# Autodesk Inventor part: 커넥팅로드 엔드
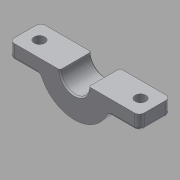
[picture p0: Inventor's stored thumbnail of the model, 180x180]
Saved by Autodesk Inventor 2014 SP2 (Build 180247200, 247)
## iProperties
Created: 2016-11
Part Number: 커넥팅로드 엔드
Material: 알루미늄 6061
Document SubType Name: Modeling
Designer: mduedu
Density: 2.71 g/cm^3
Mass: 15.0819 g
Surface Area: 26.6719 cm^2
Volume: 5.56529 cm^3
Appearance: 알루미늄 - 평지
Author: mduedu
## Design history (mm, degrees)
sketch "스케치1" dims "d0" = 30, "d3" = 15
  geometry: L1 (0, 0)-(0, 96); L2 (-5, 90.41)-(-10, 11.18); L3 (5, 90.41)-(10, 11.18); C1 r 6 at (0, 0); C2 r 4 at (0, 96); 3 further points
  constraints: 6 end point, 4 coincident, 2 centre point, 2 symmetric about line, 1 vertical, 6 other
  dimensions: "d1" = 12 diameter of C1; "d2" = 8 diameter of C2; "d4" = 96 distance of L1.start L1.end; "d6" = 10 distance from line of L1 L2.end; "d7" = 5 distance from line of L1 L2.start
extrude "돌출1" new body sketch "스케치1" stored distance "d8" = 13; taper "d9" = 0 deg
extrude "돌출2" join sketch "스케치1" stored distance "d10" = 32; taper "d11" = 0 deg
sketch "스케치2"
  geometry: L1 (5, 90.41)-(10, 11.18) reference; L2 (-5, 90.41)-(-10, 11.18) reference; A1 r 7.5 centre (0, 96) between (5, 90.41) and (-5, 90.41) reference; A2 r 15 centre (0, 0) between (10, 11.18) and (-10, 11.18) reference
extrude "돌출3" join sketch "스케치2" stored distance "d12" = 8; taper "d13" = 0 deg
sketch "스케치3"
  geometry: L1 (-2.732, 78.715)-(-6.171, 24.226); L2 (2.732, 78.715)-(6.171, 24.226); L3 (0, 78.5)-(0, 25); A1 r 17.5 centre (0, 96) between (-2.732, 78.715) and (2.732, 78.715); A2 r 25 centre (0, 0) between (6.171, 24.226) and (-6.171, 24.226); 9 further points; 2 other entities
  constraints: 6 end point, 6 point on circle, 2 centre point, 1 symmetric about line, 1 vertical alignment, 6 other
  dimensions: "d18" = 10 dimension on A1; "d19" = 10 dimension on A2; "d20" = 3 dimension on L1
extrude "돌출4" cut sketch "스케치3" distance "d21" = 2; taper "d22" = 0 deg
fillet "모깎기1" dims "d23" = 2
fillet "모깎기2" dims "d24" = 2
fillet "모깎기3" dims "d25" = 1
chamfer "모따기1" distance "d26" = 0.5; stored, may be unused: second distance "d27" = 2, angle "d28" = 45 deg
sketch "스케치4"
  geometry: L1 (-27, -6)-(-13.748, -6); L2 (27, -6)-(27, 6); L3 (27, 6)-(13.748, 6); L4 (-27, 6)-(-27, -6); L5 (-27, -6)-(27, 6); L6 (27, -6)-(-27, 6); L7 (-13.748, 6)-(-27, 6); L8 (13.748, 6)-(-13.748, 6); L9 (13.748, -6)-(27, -6); L10 (-13.748, -6)-(13.748, -6); A1 r 15 centre (0, 0) between (-13.748, 6) and (13.748, 6) reference; 1 further point
  constraints: 20 end point, 10 parallel, 4 point on circle, 3 horizontal, 3 perpendicular, 2 midpoint
  dimensions: "d29" = 54 distance of L1.start L2.start; "d31" = 12 distance of L2.start L2.end
extrude "돌출5" join sketch "스케치4" stored distance "d32" = 0; taper "d33" = 0 deg
fillet "모깎기4" dims "d34" = 2
fillet "모깎기5" dims "d35" = 1
fillet "모깎기6" dims "d36" = 1
sketch "스케치5"
  geometry: L1 (1, 0)-(1, 9) reference; L2 (-18.5, 20.5)-(-33.5, 20.5) reference; L3 (-33.5, -11.5)-(-18.5, -11.5) reference; L4 (-26, 20.5)-(-26, -11.5); 3 further points
  constraints: 2 end point, 2 midpoint, 1 horizontal alignment, 1 symmetric about line
  dimensions: "d37" = 6 distance from line of point (-5, 4.5) L1
feature "분할1"
sketch "스케치7"
  geometry: 2 further points
  constraints: 2 other
hole "구멍2" sketch "스케치7" at (-47, 4.5), (-5, 4.5) diameter "d45" = 4.5; stored, may be unused: countersink angle "d49" = 90 deg, drill point angle "d51" = 0 deg; dims "d46" = 6, "d47" = 4, "d48" = 2, "d50" = 8
node "솔리드1"
mirror "대칭1"
other parameters: "d16" = 4, "d17" = 4
